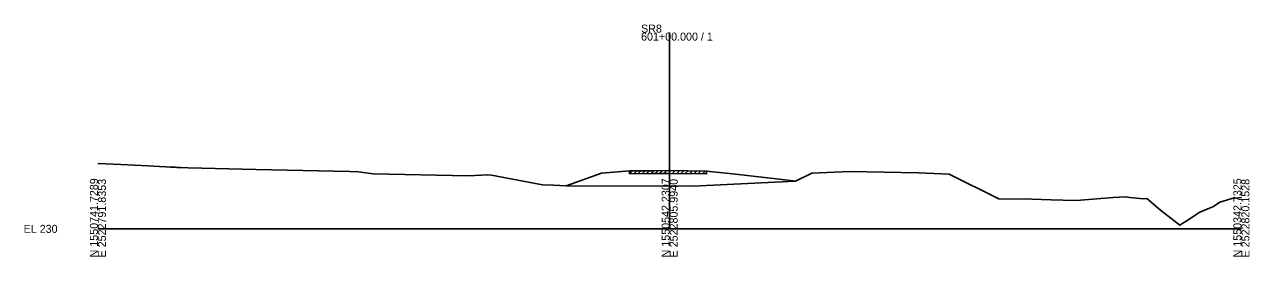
# Model space of a CAD drawing. Extents: x -26 to 2803, y -10 to 19537.
# Drawn here: x -25.7 to 402.8, y 9490.3 to 9571.5 of the extents above; entities that cross this region are included whole.
import ezdxf

# ---------------------------------------------------------------- set-up
doc = ezdxf.new("R2010")
doc.units = 0
for name, color, linetype in [('1', 7, 'Continuous'), ('Draft_XS_Grid', 7, 'Continuous'), ('Draft_XS_Text', 7, 'Continuous'), ('DTM_X_GROUND', 7, 'Continuous'), ('SLOPE_STAKES_FILL', 7, 'Continuous'), ('XS_P_SHOULDER', 7, 'Continuous')]:
    doc.layers.add(name, color=color, linetype=linetype)

msp = doc.modelspace()

# ---------------------------------------------------------------- linework, layer by layer
at = {"layer": '1'}
for p, q in [((200, 9500), (200, 9568.7)), ((0, 9500), (200, 9500)), ((200, 9500), (400, 9500))]:
    msp.add_line(p, q, dxfattribs=at)
at = {"layer": 'Draft_XS_Grid'}
for p, q in [((185.95, 9519.3), (186.96, 9520.31)), ((185.95, 9519.3), (185.95, 9520.3)), ((185.95, 9519.3), (193.89, 9519.36)), ((187.45, 9519.31), (188.46, 9520.32)), ((188.95, 9519.32), (189.96, 9520.33)), ((190.45, 9519.33), (191.46, 9520.34)), ((191.95, 9519.34), (192.96, 9520.35)), ((193.45, 9519.35), (194.46, 9520.36)), ((193.89, 9519.36), (199.58, 9519.4)), ((194.95, 9519.36), (195.96, 9520.37)), ((196.45, 9519.38), (197.46, 9520.38)), ((197.96, 9519.39), (198.96, 9520.39)), ((199.46, 9519.4), (200.45, 9520.39)), ((199.58, 9519.4), (200, 9519.39)), ((200, 9519.39), (212.93, 9519.23)), ((200.96, 9519.38), (201.94, 9520.37)), ((202.46, 9519.36), (203.44, 9520.35)), ((203.96, 9519.34), (204.95, 9520.33)), ((205.46, 9519.32), (206.45, 9520.31)), ((206.96, 9519.3), (207.95, 9520.29)), ((208.46, 9519.29), (209.45, 9520.27)), ((209.96, 9519.27), (210.95, 9520.25)), ((211.46, 9519.25), (212.45, 9520.23)), ((212.93, 9520.23), (212.93, 9519.23))]:
    msp.add_line(p, q, dxfattribs=at)
at = {"layer": 'Draft_XS_Text'}
for p, q in [((243.99, 9516.74), (249.71, 9519.51)), ((249.71, 9519.51), (263, 9520.04)), ((263, 9520.04), (275, 9519.8)), ((275, 9519.8), (287, 9519.56)), ((287, 9519.56), (297.79, 9519.13)), ((297.79, 9519.13), (315.16, 9510.47))]:
    msp.add_line(p, q, dxfattribs=at)
for points in [[(0, 9522.9), (8.01, 9522.5), (17.52, 9522.02), (21.59, 9521.81), (23.84, 9521.7), (25.27, 9521.63), (26.27, 9521.58), (26.99, 9521.54), (27.55, 9521.51), (27.99, 9521.49), (28.88, 9521.44), (31.57, 9521.34), (55.27, 9520.79), (88.07, 9520.07), (91.19, 9519.95), (96.22, 9519.27), (129.63, 9518.5), (136.37, 9518.91), (137.64, 9518.73), (155.48, 9515.46), (159.4, 9515.27), (163.74, 9515.07), (176.18, 9519.47), (185.95, 9520.3), (193.89, 9520.36), (199.58, 9520.4), (200, 9520.39), (212.93, 9520.23), (221.98, 9519.24), (223.01, 9519.13), (239.3, 9517.27), (243.99, 9516.74)], [(315.16, 9510.47), (326.73, 9510.37), (333.47, 9510.17), (341.75, 9509.92), (343.69, 9510.09), (355.19, 9511.01), (359.3, 9511.22), (360.98, 9510.97), (365.68, 9510.46), (366.91, 9510.61), (371.71, 9506.48), (378.51, 9501.26), (379.48, 9502.03), (380.31, 9502.44), (385.41, 9505.8), (390.22, 9507.86), (392.42, 9509.29), (396.3, 9510.51), (396.69, 9510.67), (400, 9510.96)]]:
    msp.add_lwpolyline(points, dxfattribs=at)
at = {"layer": 'DTM_X_GROUND'}
for p, q in [((208.11, 9514.9), (163.74, 9515.07)), ((243.99, 9516.74), (208.11, 9514.9))]:
    msp.add_line(p, q, dxfattribs=at)
at = {"layer": 'SLOPE_STAKES_FILL'}
for p, q in [((243.99, 9516.74), (249.71, 9519.51)), ((249.71, 9519.51), (263, 9520.04)), ((263, 9520.04), (275, 9519.8)), ((275, 9519.8), (287, 9519.56)), ((287, 9519.56), (297.79, 9519.13)), ((297.79, 9519.13), (315.16, 9510.47)), ((163.74, 9515.07), (208.11, 9514.9)), ((208.11, 9514.9), (243.99, 9516.74))]:
    msp.add_line(p, q, dxfattribs=at)
for points in [[(0, 9522.9), (8.01, 9522.5), (17.52, 9522.02), (21.59, 9521.81), (23.84, 9521.7), (25.27, 9521.63), (26.27, 9521.58), (26.99, 9521.54), (27.55, 9521.51), (27.99, 9521.49), (28.88, 9521.44), (31.57, 9521.34), (55.27, 9520.79), (88.07, 9520.07), (91.19, 9519.95), (96.22, 9519.27), (129.63, 9518.5), (136.37, 9518.91), (137.64, 9518.73), (155.48, 9515.46), (159.4, 9515.27), (163.74, 9515.07)], [(315.16, 9510.47), (326.73, 9510.37), (333.47, 9510.17), (341.75, 9509.92), (343.69, 9510.09), (355.19, 9511.01), (359.3, 9511.22), (360.98, 9510.97), (365.68, 9510.46), (366.91, 9510.61), (371.71, 9506.48), (378.51, 9501.26), (379.48, 9502.03), (380.31, 9502.44), (385.41, 9505.8), (390.22, 9507.86), (392.42, 9509.29), (396.3, 9510.51), (396.69, 9510.67), (400, 9510.96)]]:
    msp.add_lwpolyline(points, dxfattribs=at)
at = {"layer": 'XS_P_SHOULDER'}
for points in [[(185.95, 9519.3), (185.95, 9520.3), (176.18, 9519.47), (163.74, 9515.07), (208.11, 9514.9), (243.99, 9516.74), (239.3, 9517.27), (223.01, 9519.13), (221.98, 9519.24), (212.93, 9520.23), (212.93, 9519.23), (200, 9519.39), (199.58, 9519.4), (193.89, 9519.36)], [(193.89, 9520.36), (199.58, 9520.4), (200, 9520.39), (212.93, 9520.23), (212.93, 9519.23), (200, 9519.39), (199.58, 9519.4), (193.89, 9519.36), (185.95, 9519.3), (185.95, 9520.3)]]:
    msp.add_lwpolyline(points, close=True, dxfattribs=at)

# ---------------------------------------------------------------- texts
at = {"layer": '1'}
for s, p in [('SR8', (190, 9568.7)), ('601+00.000 / 1', (190, 9565.9)), ('EL 230', (-26, 9498.6))]:
    msp.add_text(s, height=2.8, dxfattribs=at).set_placement(p)
for s, p in [('N 1550741.7289', (0, 9490)), ('E 2522791.8353', (2.8, 9490)), ('N 1550542.2307', (200, 9490)), ('E 2522805.9940', (202.8, 9490)), ('N 1550342.7325', (400, 9490)), ('E 2522820.1528', (402.8, 9490))]:
    msp.add_text(s, height=2.8, rotation=90, dxfattribs=at).set_placement(p)

doc.saveas('drawing.dxf')
